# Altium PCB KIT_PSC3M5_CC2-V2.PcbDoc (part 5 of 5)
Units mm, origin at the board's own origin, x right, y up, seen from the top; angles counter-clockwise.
Board outline 131.5 x 87 mm, 6 copper layers (Top Layer, Int1 (GND), Int2 (Sign), Int3 (Sign), Int4 (PWR), Bottom Layer), stack 1.551 mm thick; 371 components, 253 nets, 1359 pads, 837 vias.
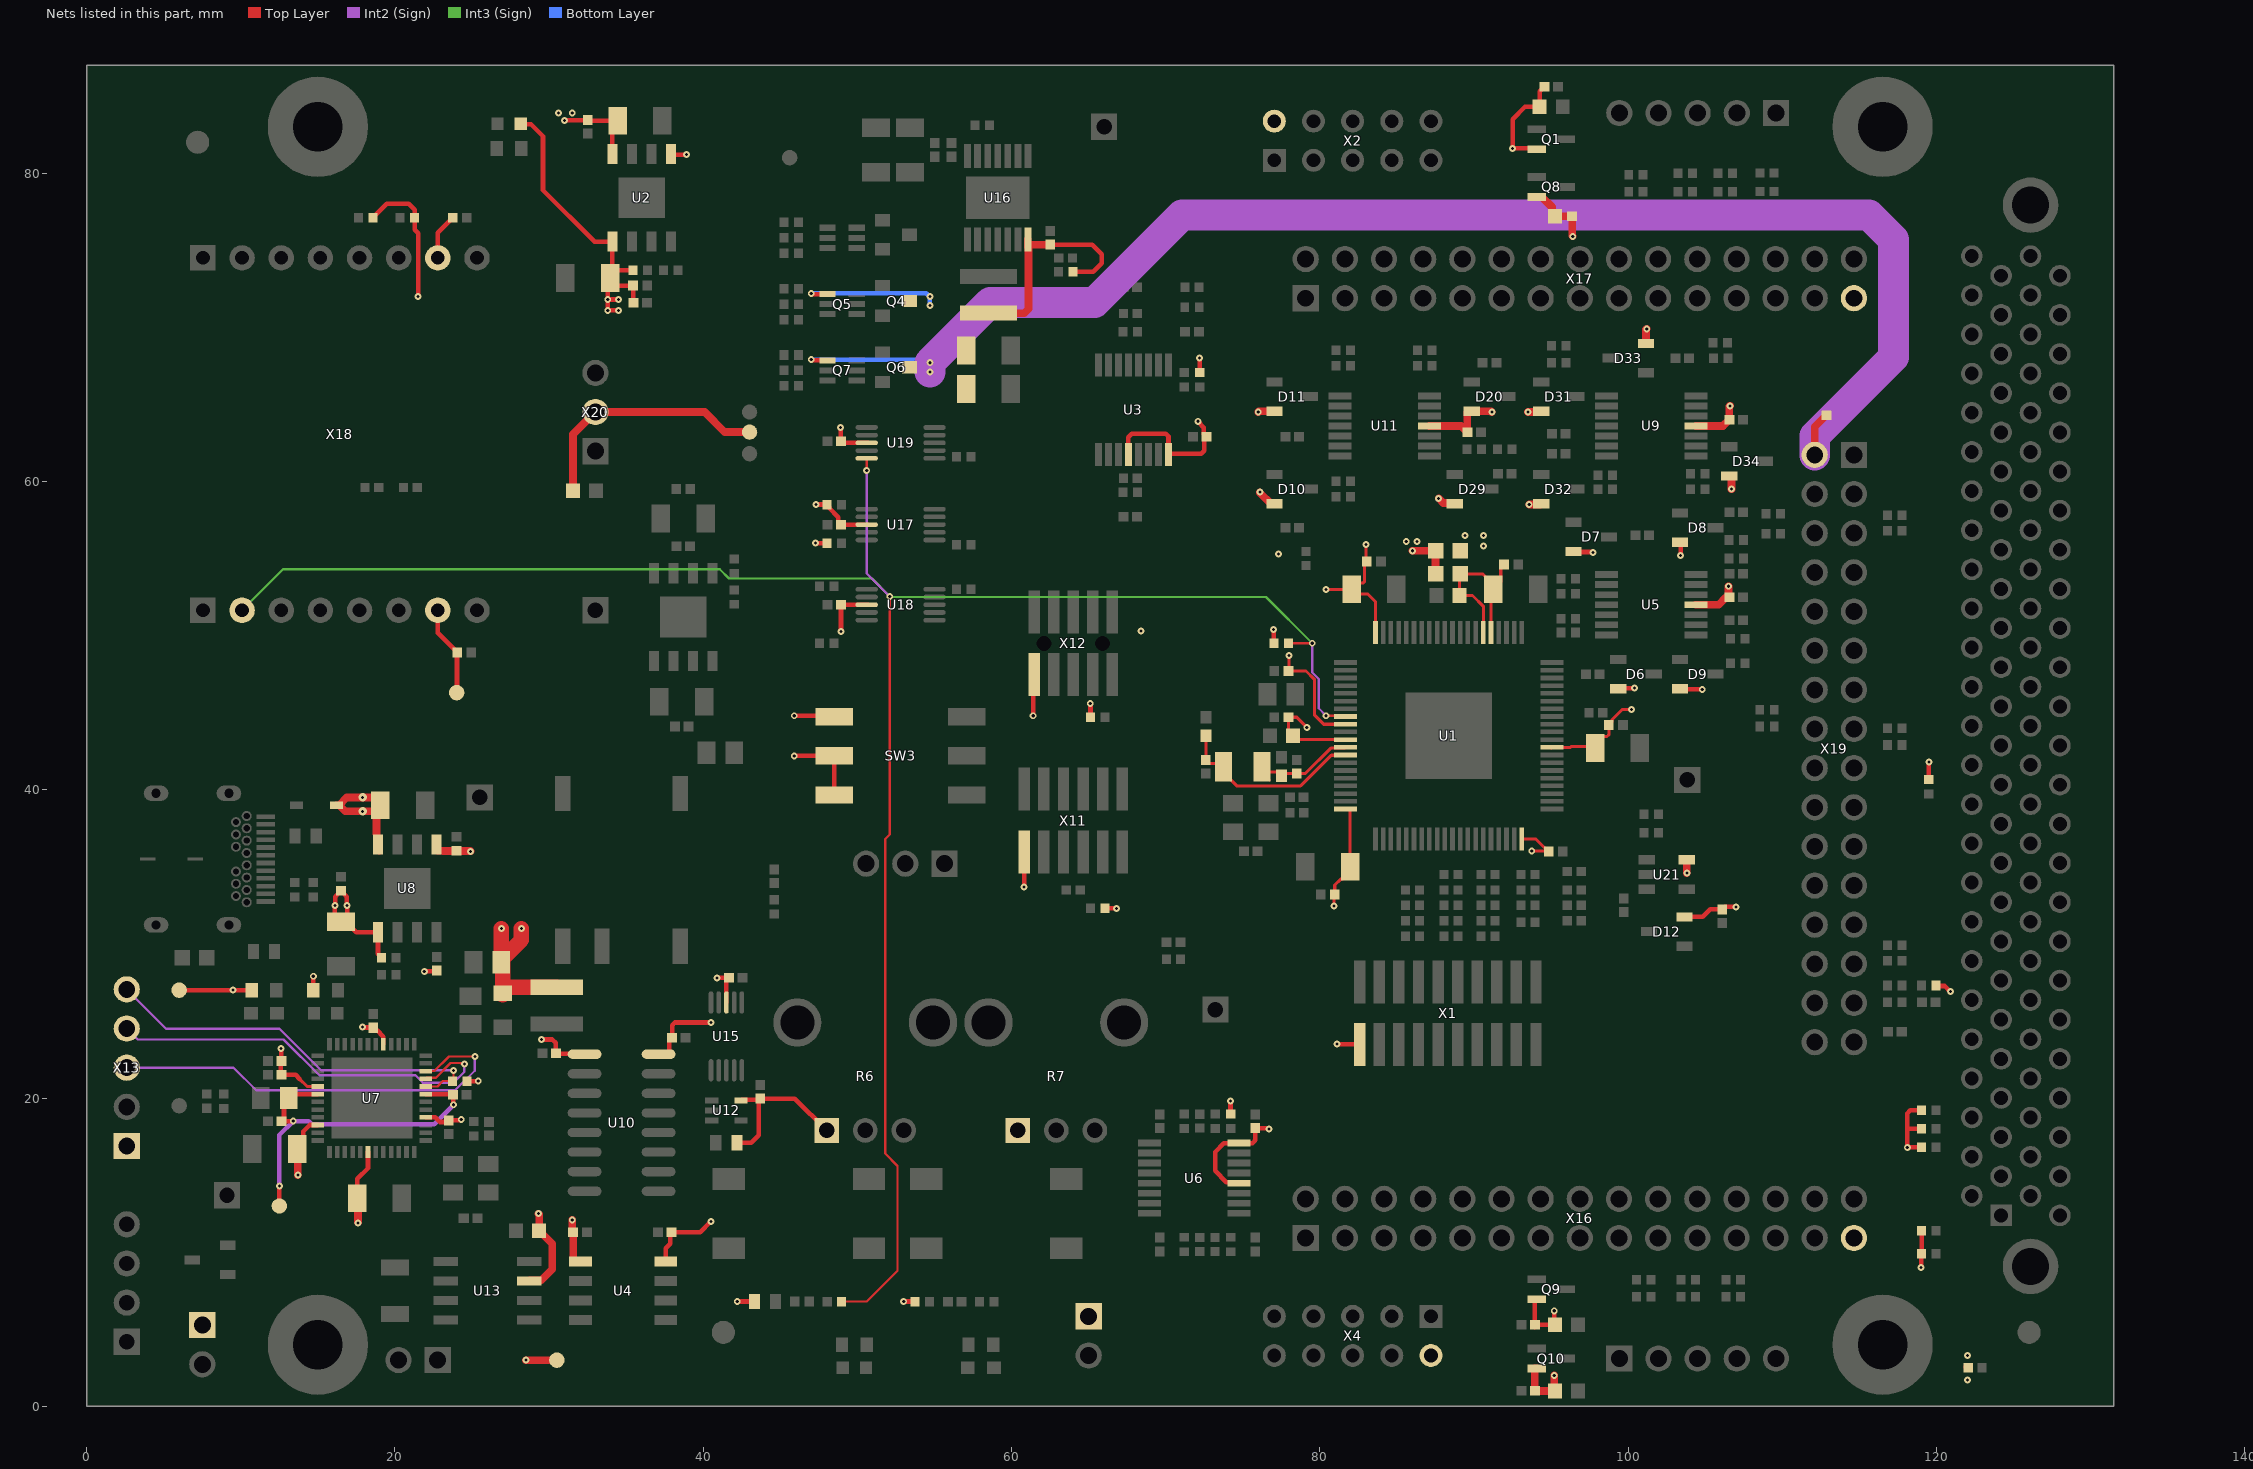
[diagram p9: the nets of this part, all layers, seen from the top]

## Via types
v1: diameter 0.45, hole 0.2, Top Layer to Bottom Layer, tented both sides, 833 vias
v2: diameter 0.55, hole 0.2, Top Layer to Bottom Layer, tented both sides, 4 vias

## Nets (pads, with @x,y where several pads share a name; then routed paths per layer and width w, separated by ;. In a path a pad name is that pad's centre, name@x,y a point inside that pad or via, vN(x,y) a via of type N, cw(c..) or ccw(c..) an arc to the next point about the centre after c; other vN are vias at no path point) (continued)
VDD3.3: C12.2 C14.2 C15.2 C20.1 C29.1 C32.1 C33.2 C34.2 C35.2 C36.2 C65.2 C75.2 C77.2 C81.2 C82.2 C124.2 C125.2 D3.2 JP1.1 L2.1 Q1.2 Q9.2 R5.2 R6.1 R7.1 R14.2 R47.2 R48.2 R49.2 R50.1 R53.2 R70.2 R75.2 R91.2 R99.2 R127.2 R133.2 R140.2 R141.2 R142.2 R143.2 R144.2 R145.2 R162.2 R163.2 SW3.4 SW3.5 SW3.6 TP7.1 U2.1 U3.12 U3.16 U4.8 U6.12 U6.16 U10.16 U12.5 U15.8 U17.8 U18.8 U19.8 X1.1 X11.1 X12.1 X16.29 X17.29 X18.7 | length 129.5
  Top Layer w0.3: R48.2@18.585,77.115 R48.2@18.57,77.1 18.57,77.12 18.71,77.26 18.73,77.26 19.47,78 20.9,78 21.27,77.63 R49.2@21.27,77.1 21.27,76.33 21.5,76.1 v1(21.5,72) ; X18.7@22.78,51.64 22.78,50.17 24.04,48.91 C75.2@24.04,48.9 24.02,48.88 24.02,46.32 TP7.1@24,46.3 ; D3.2@28.15,83.2 28.174,83.176 28.824,83.176 29.6,82.4 29.6,78.9 32.945,75.555 U2.1@34.095,75.555 C15.2@34.095,73.395 ; v1(34.5,71.1) v1(33.8,71.1) v1(33.8,71.8) ; v1(34.5,71.8) v1(33.8,71.8) ; R133.2@35.43,73.7 34.4,73.7 C15.2@34.095,73.395 ; C12.2@35.46,71.6 35.45,71.61 35.45,72.69 C14.2@35.44,72.7 34.4,72.7 33.95,73.15 C15.2@33.95,73.2 ; U10.16@37.1,22.845 37.661,22.845 37.8,22.984 37.8,23.74 C65.2@37.96,23.9 ; U4.8@37.57,9.405 37.57,10.263 37.848,10.54 37.848,11.208 C20.1@37.94,11.3 39.8,11.3 v1(40.5,12) ; C65.2@37.98,23.88 37.98,24.724 38.156,24.9 v1(40.5,24.9) ; v1(40.9,27.8) 40.908,27.808 41.652,27.808 C81.2@41.66,27.8 ; U15.8@41.5,26.2 41.5,27.7 C81.2@41.641,27.841 ; R53.2@42.19,17.1 43.1,17.1 43.6,17.6 43.6,19.86 C77.2@43.7,19.96 ; v1(42.2,6.8) R5.2@43.31,6.8 R5.2@43.305,6.795 ; U12.5@42.45,19.85 42.5,19.9 43.6,19.9 43.68,19.98 C77.2@43.7,19.96 ; C77.2@43.8,19.86 C77.2@43.7,19.96 ; v1(45.9,42.2) SW3.5@48.5,42.2 SW3.6@48.5,39.66 SW3.6@48.44,39.6 ; v1(45.9,44.8) SW3.4@48.54,44.8 ; v1(47.275,56) R70.2@47.96,56 ; v1(47.3,58.5) R127.2@47.886,58.5 ; R6.1@48,17.9 45.94,19.96 C77.2@43.7,19.96 ; R127.2@48.03,58.5 48.03,58.48 48.17,58.34 48.17,58.276 48.765,57.681 48.765,57.36 48.925,57.2 C124.2@48.94,57.2 ; v1(48.9,63.5) 48.92,63.48 48.92,62.62 C82.2@48.94,62.6 49.03,62.51 50.694,62.51 U19.8@50.705,62.5 ; v1(48.919,50.275) 48.929,50.286 48.929,51.989 C125.2@48.94,52 U18.8@50.6,52 U18.8@50.705,52 ; C124.2@49.081,57.2 U17.8@50.6,57.2 U17.8@50.705,57.2 ; v1(53,6.8) R50.1@53.73,6.8 ; v1(60.8,33.7) 60.812,33.713 60.812,35.953 X11.1@60.825,35.965 ; v1(61.4,44.8) 61.4,47.405 X12.1@61.46,47.465 ; v1(65.1,45.6) 65.115,45.585 65.115,44.715 R14.2@65.13,44.7 ; R145.2@66.07,32.3 v1(66.8,32.3) ; U3.12@67.575,61.75 67.575,62.875 67.8,63.1 69.999,63.1 70.175,62.924 U3.16@70.175,61.75 70.2,61.75 70.25,61.8 72.3,61.8 72.5,62 72.5,62.76 C29.1@72.64,62.9 72.625,62.9 72.465,63.06 72.465,63.494 72.1,63.859 v1(72.1,63.9) ; v1(72.2,68) R75.2@72.2,67.07 R75.2@72.34,66.93 ; R91.2@74.2,18.97 v1(74.2,19.8) ; U6.12@74.75,14.475 74.675,14.55 73.926,14.55 73.2,15.276 73.2,16.5 73.757,17.057 74.732,17.057 U6.16@74.75,17.075 75.624,17.075 75.8,17.251 C32.1@75.8,18.06 75.831,18.029 76.671,18.029 v1(76.7,18) ; v1(77,50.4) 77.015,50.385 77.015,49.515 R99.2@77.03,49.5 ; v1(81.1,23.5) 82.55,23.5 X1.1@82.585,23.465 ; C36.2@93.94,5.15 Q9.2@93.94,6.95 ; C36.2@93.94,5.3 C35.2@95.25,5.3 ; Q1.2@94,81.55 93.95,81.6 v1(92.5,81.6) 92.5,83.5 93.3,84.3 C33.2@94.25,84.3 94.25,85.305 94.545,85.6 C34.2@94.56,85.6 ; C35.2@95.2,5.3 v1(95.2,6.2) ; v1(119,9) 119.015,9.015 119.015,9.885 R141.2@119.03,9.9 R142.2@119.03,11.4 R142.2@119.015,11.415 ; R140.2@119.03,16.8 v1(118.1,16.8) 118.1,18 ; R144.2@119.03,18 118.1,18 ; R143.2@119.03,19.2 118.3,19.2 118.1,19 118.1,18 ; R162.2@119.5,40.67 v1(119.5,41.8) ; R163.2@119.97,27.3 120.004,27.266 120.534,27.266 v1(120.9,26.9) ; v1(33.8,71.8) 33.8,73.05 C15.2@33.95,73.2 ; C15.2@33.95,73.2 33.95,73.25 C15.2@34.095,73.395 ; C15.2@33.95,73.2 34.095,73.345 C15.2@34.095,73.395
  Top Layer w0.5: R47.2@122,2.55 R47.2@122.05,2.5
  Int2 (Sign) w0.3: v1(77,50.4) v1@77,50.454
  Int3 (Sign) w0.3: v1@76.946,50.4 v1(77,50.4)
  other v1: 122,1.7 122,3.3 68.4,50.3 77.3,55.3 90.6,55.8 89.4,56.5 90.6,56.5
VDD5: C13.2 C22.2 C23.2 C24.2 C25.2 C37.2 C38.2 C39.2 C40.2 C76.2 C107.2 C131.2 D6.2 D7.2 D8.2 D9.2 D10.2 D11.2 D12.2 D20.2 D29.2 D31.2 D32.2 D33.2 D34.2 Q8.2 Q10.2 TP8.1 U2.5 U2.8 U5.4 U9.4 U11.4 U21.5 X2.2 X4.2 X18.10 X20.2 | length 62.9
  Top Layer w0.3: X18.10@22.78,74.5 22.78,76.13 23.74,77.09 C76.2@23.74,77.1 ; v1(31,83.4) 31.02,83.42 32.48,83.42 C131.2@32.5,83.44 ; C131.2@32.5,83.4 C13.2@34.45,83.4 34.095,83.045 U2.8@34.095,81.245 ; U2.5@37.905,80.915 U2.5@37.905,81.2 ; v1(38.9,81.2) U2.5@37.95,81.2 ; D7.2@96.467,55.449 96.492,55.425 97.675,55.425 v1(97.7,55.4) ; D6.2@99.35,46.55 99.375,46.575 100.375,46.575 v1(100.4,46.6) ; D9.2@103.35,46.55 103.375,46.525 104.775,46.525 v1(104.8,46.5) ; D8.2@103.35,56.05 103.4,56 v1(103.4,55.2) ; D12.2@103.675,31.725 D12.2@103.65,31.75 104.825,31.75 105.315,32.24 C25.2@106.1,32.24 106.26,32.4 v1(107,32.4) ; U2.5@37.905,81.2 U2.5@37.95,81.2 ; U2.5@37.905,81.2 U2.5@37.905,81.245 U2.5@37.95,81.2
  Top Layer w0.5: C107.2@31.55,59.4 31.55,63.05 X20.2@33,64.5 40.1,64.5 41.4,63.2 TP8.1@43,63.2 ; v1(76,64.5) 76.05,64.55 D11.2@77.05,64.55 ; v1(76.1,59.3) 76.1,59.275 76.825,58.55 D10.2@77.05,58.55 ; U11.4@87.1,63.6 89.145,63.6 89.545,63.2 C24.2@89.56,63.2 89.56,64.485 89.625,64.55 D20.2@89.85,64.55 91.1,64.55 v1(91.15,64.5) ; v1(87.7,58.9) 88,58.6 88.7,58.6 D29.2@88.75,58.55 ; v1(93.5,64.5) 94.3,64.5 D31.2@94.35,64.55 ; v1(93.575,58.5) 94.3,58.5 D32.2@94.35,58.55 ; Q10.2@94.05,2.45 93.94,2.45 C40.2@93.94,1 C39.2@95.25,1 95.2,1.05 v1(95.2,2) ; Q8.2@94.05,78.45 94.4,78.45 95.05,77.8 95.05,77.4 C37.2@95.25,77.2 C38.2@96.36,77.2 96.36,75.94 v1(96.4,75.9) ; D33.2@101.15,68.95 101.15,69.85 v1(101.2,69.9) ; v1(103.8,34.6) U21.5@103.8,35.45 ; U5.4@104.4,52 105.859,52 106.299,52.44 106.5,52.44 C22.2@106.56,52.5 106.5,52.56 v1(106.5,53.2) ; U9.4@104.4,63.6 106.145,63.6 106.545,64 C23.2@106.56,64 106.56,64.86 v1(106.6,64.9) ; D34.2@106.55,60.35 106.65,60.35 106.7,60.3 v1(106.7,59.5)
  other v1: 30.6,83.9 31.5,83.9
VDDA: C11.2 C16.2 C17.2 L4.2 U1.65 U1.66 | length 12.9
  Top Layer w0.2: C17.2@89.333,52.717 C17.2@89.05,53 ; U1.66@90.6,50.2 90.6,51.9 89.9,52.6 C17.2@89.05,52.6 C17.2@89.05,53 ; C11.2@90.95,53 91.1,52.85 U1.65@91.1,50.2 ; C16.2@91.94,54.61 C16.2@91.94,54.6 91.73,54.39 91.73,53.48 C11.2@91.25,53 91.25,53.3 90.55,54 L4.2@89.1,54 89.05,53.95 C17.2@89.05,53
VDDC: C51.2 C52.2 C53.2 TP4.1 U7.6 U7.31 | length 23.8
  Top Layer w0.3: TP4.1@12.5,13 v1(12.5,14.3) ; v1(13.4,18.502) C52.2@12.64,18.502 12.801,18.662 12.801,19.703 13.348,20.25 U7.6@15,20.25 ; U7.31@22,20.25 23.71,20.25 C53.2@23.76,20.2 23.78,20.18 23.78,19.585 v1(23.8,19.565)
  Int2 (Sign) w0.3: v1(12.5,14.3) 12.5,17.602 v1(13.4,18.502) 14.4,18.502 14.6,18.302 22.537,18.302 v1(23.8,19.565)
VDDIO: C1.2 C2.2 C3.2 C4.2 C5.2 C6.2 C7.2 C8.2 C9.2 C10.2 L2.2 L4.1 U1.9 U1.11 U1.20 U1.40 U1.49 U1.80 | length 43
  Top Layer w0.15: U1.49@94.975,42.725 U1.49@95,42.7
  Top Layer w0.2: v1(78,48.7) 78,47.74 C8.2@77.96,47.7 79.1,47.7 79.636,47.164 79.636,44.857 80.243,44.25 U1.9@81.65,44.25 ; v1(79.146,44.046) 79.146,44.054 78.5,44.7 C1.2@77.96,44.7 77.96,43.79 C2.2@78.25,43.5 78.5,43.25 U1.11@81.65,43.25 ; v1(80.4,53) C5.2@82.05,53 ; v1(80.9,32.45) 80.9,33.14 C10.2@80.96,33.2 80.96,33.82 81.34,34.2 81.45,34.2 81.95,34.7 C3.2@81.95,35 81.95,38.7 81.9,38.75 U1.20@81.65,38.75 ; v1(83,55.9) 83,54.84 C6.2@83.04,54.8 82.9,54.66 82.9,53.517 82.783,53.4 82.45,53.4 C5.2@82.05,53 ; U1.80@83.6,50.2 83.6,52.2 83.1,52.7 82.35,52.7 C5.2@82.05,53 ; U1.40@93.1,36.8 94,36.8 94.58,36.22 94.63,36.22 94.857,35.993 C7.2@94.857,35.943 ; v1(93.739,36.025) 94.815,36.025 C7.2@94.84,36 ; U1.49@95.05,42.75 96.243,42.75 96.293,42.8 97.75,42.8 C4.2@97.85,42.7 97.85,42.952 98.35,43.452 98.623,43.452 98.74,43.569 C9.2@98.74,44.2 98.95,44.41 98.95,44.55 99.6,45.2 v1(100.2,45.2)
  Top Layer w0.5: v1(86,55.5) L2.2@87.5,55.5 L4.1@87.5,54
  other v1: 85.6,56.1 86.3,56.1
VISO3V3: C41.2 C43.2 C44.2 C45.2 C46.2 C47.2 C48.2 C49.2 C50.2 C63.2 R27.2 R112.1 R113.2 R135.2 TP2.1 U7.5 U7.10 U7.18 U7.28 U7.41 U8.1 U10.1 X13.1 | length 38.2
  Top Layer w0.2: 13.827,21.227 14.304,20.75 U7.5@15,20.75
  Top Layer w0.3: TP2.1@6,27 v1(9.5,27) R112.1@10.7,27 ; v1(12.6,23.202) 12.62,23.182 12.62,22.482 12.67,22.432 12.6,22.362 12.6,21.5 13.554,21.5 13.827,21.227 ; C47.2@13.674,16.502 14.058,16.886 14.058,17.83 14.478,18.25 U7.10@15,18.25 ; R113.2@14.7,27 v1(14.7,27.9) ; C43.2@16.44,33.38 C43.2@16.5,33.44 ; C44.2@16.5,31.45 C44.2@16.525,31.475 ; C45.2@17.55,13.5 17.55,14.752 18.25,15.452 U7.18@18.25,16.5 ; v1(17.9,24.6) 17.92,24.58 18.58,24.58 C49.2@18.6,24.56 18.6,24.545 18.76,24.385 18.839,24.385 19.25,23.974 U7.41@19.25,23.5 ; U8.1@18.828,30.688 U8.1@18.895,30.755 ; R135.2@19.13,29.1 19.13,29.12 18.895,29.355 U8.1@18.895,30.755 ; v1(21.9,28.2) 21.929,28.229 22.669,28.229 C41.2@22.7,28.26 C41.2@22.632,28.328 ; U7.28@22,18.75 22.25,18.75 22.262,18.762 22.599,18.762 22.916,18.445 23.405,18.445 C48.2@23.5,18.54 23.53,18.57 24.27,18.57 v1(24.3,18.6) ; R27.2@24.67,21.1 24.671,21.101 25.399,21.101 v1(25.4,21.102) ; v1(29.5,23.8) 30.2,23.8 30.42,23.58 30.42,22.92 30.468,22.872 32.272,22.872 U10.1@32.3,22.845 ; C43.2@16.5,33.44 16.51,33.44 16.67,33.28 16.67,33.27 16.871,33.069 16.871,32.529 v1(16.9,32.5) 16.9,31.85 C44.2@16.525,31.475 ; C43.2@16.5,33.44 16.49,33.44 16.33,33.28 16.33,33.27 16.129,33.069 16.129,32.529 v1(16.1,32.5) 16.1,31.9 C44.2@16.525,31.475 ; C44.2@16.525,31.475 16.775,31.475 17.495,30.755 U8.1@18.895,30.755
  Top Layer w0.5: C47.2@13.65,16.702 13.7,16.652 v1(13.7,15.002) ; v1@17.6,11.95 C45.2@17.6,13.4
  other v1: 17.6,11.902
VISO5: C19.1 C21.2 C42.2 C64.2 C132.2 D21.1 L5.1 L6.1 TP1.1 U4.1 U8.5 U8.8 U13.3 X30.1 | length 33.2
  Top Layer w0.5: D21.1@16.2,39 D21.1@16.375,39 ; U8.8@18.97,36.04 18.97,36.37 18.82,36.52 18.82,37.123 18.8,37.143 C42.2@18.8,38.7 ; U8.5@22.705,36.442 22.78,36.06 22.835,36.06 23.139,36.024 ccw(c23.199,36.52) 23.197,36.02 24.88,36.02 v1(24.9,36) ; v1(28.5,3) TP1.1@30.5,3 ; U13.3@28.7,8.135 28.75,8.185 29.485,8.185 30.2,8.9 30.2,10.55 29.575,11.175 29.55,11.175 29.35,11.375 C21.2@29.35,11.4 29.35,12.45 v1(29.3,12.5) ; v1(31.5,12.1) 31.5,11.36 C19.1@31.56,11.3 31.56,9.48 31.635,9.405 U4.1@32.03,9.405 ; D21.1@16.375,39 16.775,38.6 v2(17.9,38.6) 18.7,38.6 C42.2@18.8,38.7 ; D21.1@16.375,39 16.875,39.5 v2(17.9,39.5) 18.7,39.5 19.1,39.1 C42.2@19.1,39.05 ; C42.2@18.8,38.7 18.8,38.75 C42.2@19.05,39 C42.2@19.1,39.05 ; C42.2@18.8,38.7 19.1,39 C42.2@19.1,39.05
  Top Layer w1: C64.2@26.9,28.8 26.9,28.95 C64.2@26.95,29 ; v1(26.9,31) 26.9,29.05 C64.2@26.95,29 ; L5.1@27,26.7 27,28.95 C64.2@26.95,29 ; L5.1@27.435,27.185 L6.1@30.5,27.185 ; v1(28.2,31) 28.2,30.25 C64.2@26.95,29
VPWR5V: C78.1 Q6.3 Q7.1 X19.2 | length 95.6
  Top Layer w0.3: v1(47,67.9) 47.05,67.85 Q7.1@48.05,67.85
  Top Layer w0.5: X19.2@112.096,61.722 112.096,63.551 112.845,64.3 C78.1@112.86,64.3
  Int2 (Sign) w2: v1(54.7,67.1) v1(54.7,67.7) 58.61,71.61 65.39,71.61 71.054,77.275 115.625,77.275 117.2,75.7 117.2,68.055 112.096,62.951 X19.2@112.096,61.722
  Bottom Layer w0.3: v1(47,67.9) 54.459,67.9 54.659,67.7 v1(54.7,67.7)
VSW5V: C104.2 C105.2 C106.2 L3.2 Q4.3 Q5.1 R106.2 U16.14 | length 24.4
  Top Layer w0.3: v1(47,72.2) 47.05,72.15 Q5.1@48.05,72.15 ; C104.2@62.5,75.36 65.218,75.36 65.85,74.728 65.85,74.15 65.3,73.6 R106.2@63.97,73.6
  Top Layer w0.5: L3.2@58.5,70.915 60.807,70.915 61.1,71.208 61.1,75.15 61.05,75.2 U16.14@61.05,75.7 ; U16.14@61.1,75.36 C104.2@62.5,75.36
  Bottom Layer w0.3: v1(47,72.2) 54.459,72.2 54.659,72 v1(54.7,72) v1(54.7,71.4)
WCO_IN: C73.2 R2.1 U1.13 Y3.2 | length 12.4
  Top Layer w0.2: R2.1@72.6,43.5 C73.2@72.6,41.94 72.6,41.925 72.81,41.715 73.535,41.715 Y3.2@73.75,41.5 73.75,41.1 74.6,40.25 78.75,40.25 80.738,42.238 81.638,42.238 U1.13@81.65,42.25
WCO_OUT: C70.2 R1.2 U1.12 Y3.1 | length 7.1
  Top Layer w0.15: Y3.1@76.25,41.1 Y3.1@76.725,40.625
  Top Layer w0.2: Y3.1@76.25,41.5 76.6,41.15 77.25,41.15 R1.2@77.5,40.9 77.66,41.06 79.065,41.06 80.705,42.7 81.6,42.7 U1.12@81.65,42.75
XMC42_RST#: R27.1 U7.32 X13.5 | length 26
  Top Layer w0.15: U7.32@22,20.75 22.75,20.75 23.1,21.1 R27.1@23.73,21.1 23.8,21.17 v1(23.8,21.8)
  Int2 (Sign) w0.15: X13.5@2.6,27.05 5.15,24.5 12.5,24.5 15.2,21.8 v1(23.8,21.8)
XMC42_TCK: U7.34 X13.3 | length 28.2
  Top Layer w0.15: U7.34@22,21.75 22.55,21.75 23.5,22.7 v1(25.2,22.7)
  Int2 (Sign) w0.15: X13.3@2.6,21.97 9.53,21.97 11,20.5 23.9,20.5 25.174,21.774 25.174,22.674 v1(25.2,22.7)
XMC42_TMS: U7.33 X13.4 | length 27.1
  Top Layer w0.15: U7.33@22,21.25 22.059,21.309 22.637,21.309 23.603,22.275 24.237,22.275 24.245,22.267 24.433,22.267 v1(24.5,22.2)
  Int2 (Sign) w0.15: X13.4@2.6,24.51 3.31,23.8 12.776,23.8 15.101,21.475 21.325,21.475 21.8,21 23.8,21 24.5,21.7 v1(24.5,22.2)
XRES_L: R99.1 R126.2 U1.8 U19.10 X18.2 | length 138.7
  Top Layer w0.15: R126.2@48.96,6.8 50.6,6.8 52.6,8.8 52.6,15.6 51.8,16.4 51.8,36.8 52.093,37.093 v1(52.093,52.541) ; v1(50.6,60.7) U19.10@50.6,61.5 ; R99.1@77.97,49.5 v1(79.5,49.5) ; v1(80.4,44.8) U1.8@81.7,44.8
  Int2 (Sign) w0.15: v1(50.6,60.7) 50.6,54.034 v1(52.093,52.541) ; v1(79.5,49.5) 79.5,47.6 79.921,47.179 79.921,45.279 v1(80.4,44.8)
  Int3 (Sign) w0.15: X18.2@10.08,51.64 12.74,54.3 41.072,54.3 41.672,53.7 50.934,53.7 v1(52.093,52.541) 52.134,52.5 76.5,52.5 v1(79.5,49.5)
pads on no net: ADJ_1.ADJ ADJ_2.ADJ ADJ_3.ADJ R6.MH1 R6.MH2 R7.MH1 R7.MH2 U2.3 U2.7 U3.13 U3.14 U3.15 U6.13 U6.14 U6.15 U7.2 U7.8 U7.9 U7.19 U7.21 U7.24 U7.25 U7.26 U7.38 U7.42 U7.43 U7.44 U8.3 U8.7 U13.5 U14.3 U14.7 U15.7 U15.9 U16.1 U16.3 U19.4 U19.6 U19.7 U20.8 X1.7 X1.11 X1.13 X2.1 X2.4 X4.1 X4.4 X10.A2 X10.A3 X10.A8 X10.A10 X10.A11 X10.B2 X10.B3 X10.B8 X10.B10 X10.B11 X12. X12.7 X15.A26 X15.A27 X15.A32 X15.A37 X15.A38 X15.A39 X15.A40 X15.A44 X15.A48 X15.B26 X15.B27 X15.B32 X15.B37 X15.B38 X15.B39 X15.B40 X15.B42 X15.B43 X15.B47

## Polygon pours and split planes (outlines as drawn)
VDDIO on Top Layer "VDDIO_L01_P051" (solid, remove dead copper, pour order 51): 85.2,56.5 85.2,55.3 87,53.5 88.1,53.5 88.1,56.5
NetL3_1 on Top Layer "NETL3_1_L01_P065" (solid, remove dead copper, pour order 65): 58.2,76.5 59.3,76.5 59.3,74.2 59.7,73.8 60.4,73.8 60.4,72.7 56.6,72.7 56.6,73.8 57.8,73.8 58.2,74.2
VDCDC5 on Top Layer "VDCDC5_L01_P066" (solid, remove dead copper, pour order 66): 38.7,62.4 38.7,55 39.5,55 40.1,54.4 40.1,53.3 41.4,53.3 41.4,54.5 42.4,54.5 42.4,57.3 40,59.7 40,62.4
VSW5V on Top Layer "VSW5V_L01_P068" (solid, remove dead copper, pour order 68): 52.9,72.3 52.9,71.1 56,68 56,65 58,65 58,70.4 60.4,70.4 60.4,71.4 55.9,71.4 55,72.3
VDD5 on Top Layer "VDD5_L01_P069" (solid, remove dead copper, pour order 69): 30.3,84.3 34.7,84.3 34.7,80.5 33,80.5 33,83 30.3,83
VDD3.3 on Top Layer "VDD3.3_L01_P070" (solid, remove dead copper, pour order 70): 33.3,76.2 33.3,70.8 35.8,70.8 35.8,74.5 34.7,74.5 34.7,76.2
VISO5 on Top Layer "VISO5_L01_P071" (solid, remove dead copper, pour order 71): 19.5,40 19.5,35.8 18,35.8 18,38.2 15.7,38.2 15.7,40
VISO3V3 on Top Layer "VISO3V3_L01_P072" (solid, remove dead copper, pour order 72): 15.6,33.7 15.6,30 19.4,30 19.4,31.5 17.2,33.7
VDDA on Top Layer "VDDA_L01_P054" (solid, remove dead copper, pour order 54): 88.5,54.6 88.5,51.9 90.1,51.9 90.4,51.6 90.4,49.3 91.3,49.3 91.3,51.3 92.3,52.3 92.3,55 91.5,55 91.1,54.6
VDD3.3 on Top Layer "VDD3.3_L01_P064" (solid, remove dead copper, pour order 64): 88.5,57 88.5,54.8 91,54.8 91,57
VDCDC7 on Top Layer "VDCDC7_L01_P067" (solid, remove dead copper, pour order 67): 38,38.5 38,47.3 39.5,47.3 39.5,49 41,49 41,38.5
GNDISO on Top Layer "GNDISO_L01_P080" (solid, remove dead copper, pour order 80): 0.5,40.5 24.7,40.5 31.9,33.3 31.9,5.4 27,0.5 0.5,0.5
GND on Top Layer "GND_L01_P079" (solid, remove dead copper, pour order 79): 0.5,86.5 0.5,51 6.3,45.2 35.1,45.2 38,42.3 38,28.6 38,15.3 37.6,14.9 37.6,0.5 131,0.5 131,86.5
GNDISO on Bottom Layer "GNDISO_L06_P078" (solid, remove dead copper, pour order 78): 0.5,40.5 24.7,40.5 31.9,33.3 31.9,5.4 27,0.5 0.5,0.5
GND on Bottom Layer "GND_L06_P077" (solid, remove dead copper, pour order 77): 0.5,86.5 0.5,51 6.3,45.2 35.1,45.2 38,42.3 38,28.6 38,15.3 37.6,14.9 37.6,0.5 131,0.5 131,86.5
GNDISO on Int2 (Sign) "GNDISO_L03_P074" (solid, remove dead copper, pour order 74): 0.5,40.5 24.7,40.5 31.9,33.3 31.9,5.4 27,0.5 0.5,0.5
GND on Int2 (Sign) "GND_L03_P073" (solid, remove dead copper, pour order 73): 0.5,86.5 0.5,51 6.3,45.2 35.1,45.2 38,42.3 38,28.6 38,15.3 37.6,14.9 37.6,0.5 131,0.5 131,86.5
GNDISO on Int3 (Sign) "GNDISO_L04_P076" (solid, remove dead copper, pour order 76): 0.5,40.5 24.7,40.5 31.9,33.3 31.9,5.4 27,0.5 0.5,0.5
GND on Int3 (Sign) "GND_L04_P075" (solid, remove dead copper, pour order 75): 0.5,86.5 0.5,51 6.3,45.2 35.1,45.2 38,42.3 38,28.6 38,15.3 37.6,14.9 37.6,0.5 131,0.5 131,86.5
VDD5 on Int4 (PWR) (split plane): 53.898,75 53.906,74.961 53.928,74.928 53.961,74.906 54,74.898 56,74.898 56.039,74.906 56.072,74.928 56.094,74.961 56.102,75 56.102,84.398 89.898,84.398 89.898,77 89.906,76.961 89.928,76.928 89.961,76.906 90,76.898 107.898,76.898 107.898,31.102 101.902,31.102 101.902,35.6 101.902,44.4 101.894,44.439 101.872,44.472 91.102,55.242 91.102,56.8 91.094,56.839 91.072,56.872 89.472,58.472 89.439,58.494 89.4,58.502 74.602,58.502 74.602,73 74.594,73.039 74.572,73.072 74.539,73.094 74.5,73.102 32.5,73.102 32.461,73.094 32.428,73.072 32.406,73.039 32.398,73 32.398,70.5 32.406,70.461 32.428,70.428 34.398,68.458 34.398,63.302 30.602,63.302 30.602,73 30.594,73.039 30.572,73.072 30.539,73.094 30.5,73.102 2,73.102 1.961,73.094 1.928,73.072 1.906,73.039 1.898,73 1.898,52.5 1.906,52.461 1.928,52.428 4.928,49.428 4.961,49.406 5,49.398 37.858,49.398 39.898,47.358 39.898,4.5 39.906,4.461 39.928,4.428 39.961,4.406 40,4.398 96.398,4.398 96.398,0.51 38,0.51 38,42.3 35.1,45.2 6.3,45.2 0.51,50.99 0.51,86.49 53.898,86.49
VISO3V3 on Int4 (PWR) (split plane): 16.898,37.5 16.906,37.461 16.928,37.428 16.961,37.406 17,37.398 21.958,37.398 25.898,33.458 25.898,30 25.906,29.961 25.928,29.928 25.961,29.906 26,29.898 29.898,29.898 29.898,14.042 26.458,10.602 9.542,10.602 6.572,13.572 6.539,13.594 6.5,13.602 0.51,13.602 0.51,40.5 16.898,40.5
VISO5 on Int4 (PWR) (split plane): 31.9,35.1 31.9,5.4 27.01,0.51 0.51,0.51 0.51,13.398 6.458,13.398 9.428,10.428 9.461,10.406 9.5,10.398 26.5,10.398 26.539,10.406 26.572,10.428 30.072,13.928 30.094,13.961 30.102,14 30.102,30 30.094,30.039 30.072,30.072 30.039,30.094 30,30.102 26.102,30.102 26.102,33.5 26.094,33.539 26.072,33.572 22.072,37.572 22.039,37.594 22,37.602 17.102,37.602 17.102,40.5 26.5,40.5
VDD3.3 on Int4 (PWR) (split plane): 113.298,73.16 113.306,73.121 113.328,73.088 113.361,73.066 113.4,73.058 128.398,73.058 128.398,25.102 125,25.102 124.961,25.094 124.928,25.072 124.906,25.039 124.898,25 124.898,18.952 120.848,14.902 113.4,14.902 113.361,14.894 113.328,14.872 113.306,14.839 113.298,14.8 113.298,12.2 113.306,12.161 113.328,12.128 113.361,12.106 113.4,12.098 130.99,12.098 130.99,0.51 96.602,0.51 96.602,4.5 96.594,4.539 96.572,4.572 96.539,4.594 96.5,4.602 40.102,4.602 40.102,47.4 40.094,47.439 40.072,47.472 37.972,49.572 37.939,49.594 37.9,49.602 5.042,49.602 2.102,52.542 2.102,72.898 30.398,72.898 30.398,63.2 30.406,63.161 30.428,63.128 30.461,63.106 30.5,63.098 34.5,63.098 34.539,63.106 34.572,63.128 34.594,63.161 34.602,63.2 34.602,68.5 34.594,68.539 34.572,68.572 32.602,70.542 32.602,72.898 74.398,72.898 74.398,58.4 74.406,58.361 74.428,58.328 74.461,58.306 74.5,58.298 89.358,58.298 90.898,56.758 90.898,55.302 87.202,55.302 87.202,56.5 87.194,56.539 87.172,56.572 87.139,56.594 87.1,56.602 79.7,56.602 79.661,56.594 79.628,56.572 79.606,56.539 79.598,56.5 79.598,52.142 77.028,49.572 77.006,49.539 76.998,49.5 76.998,34.2 76.998,31.2 77.006,31.161 77.028,31.128 77.828,30.328 77.861,30.306 77.9,30.298 82.2,30.298 82.239,30.306 82.272,30.328 87.442,35.498 101.698,35.498 101.698,31 101.706,30.961 101.728,30.928 101.761,30.906 101.8,30.898 108,30.898 108.039,30.906 108.072,30.928 108.094,30.961 108.102,31 108.102,77 108.094,77.039 108.072,77.072 108.039,77.094 108,77.102 90.102,77.102 90.102,84.398 113.298,84.398
VDDIO on Int4 (PWR) (split plane): 86.998,55.2 87.006,55.161 87.028,55.128 87.061,55.106 87.1,55.098 90.958,55.098 101.698,44.358 101.698,35.702 87.4,35.702 87.361,35.694 87.328,35.672 82.158,30.502 77.942,30.502 77.202,31.242 77.202,34.2 77.202,49.458 79.772,52.028 79.794,52.061 79.802,52.1 79.802,56.398 86.998,56.398
PWR_IN_5V on Int4 (PWR) (split plane): 130.99,12.302 113.502,12.302 113.502,14.698 120.89,14.698 120.929,14.706 120.962,14.728 125.072,18.838 125.094,18.871 125.102,18.91 125.102,24.898 128.5,24.898 128.539,24.906 128.572,24.928 128.594,24.961 128.602,25 128.602,73.16 128.594,73.199 128.572,73.232 128.539,73.254 128.5,73.262 113.502,73.262 113.502,84.5 113.494,84.539 113.472,84.572 113.439,84.594 113.4,84.602 56,84.602 55.961,84.594 55.928,84.572 55.906,84.539 55.898,84.5 55.898,75.102 54.102,75.102 54.102,86.49 130.99,86.49
GNDISO on Int1 (GND) (split plane): 26.5,40.5 31.9,35.1 31.9,5.4 27.01,0.51 0.51,0.51 0.51,40.5
GND on Int1 (GND) (split plane): 130.99,0.51 38,0.51 38,42.3 35.1,45.2 6.3,45.2 0.51,50.99 0.51,86.49 130.99,86.49
AGND on Int1 (GND) (split plane): 129.198,71.358 129.198,68.142 127.158,66.102 125.742,66.102 125.172,66.672 125.139,66.694 125.1,66.702 123.5,66.702 123.461,66.694 123.428,66.672 123.028,66.272 123.006,66.239 122.998,66.2 122.998,60.6 122.998,55.7 123.006,55.661 123.028,55.628 126.798,51.858 126.798,24.142 125.128,22.472 125.106,22.439 125.098,22.4 125.098,19.242 124.758,18.902 124.1,18.902 124.061,18.894 124.028,18.872 122.558,17.402 120.742,17.402 120.502,17.642 120.502,21.958 121.042,22.498 123.1,22.498 123.139,22.506 123.172,22.528 124.672,24.028 124.694,24.061 124.702,24.1 124.702,25.6 124.694,25.639 124.672,25.672 122.572,27.772 122.539,27.794 122.5,27.802 119.4,27.802 119.361,27.794 119.328,27.772 118.128,26.572 118.106,26.539 118.098,26.502 116.242,26.502 114.872,27.872 114.839,27.894 114.8,27.902 99.342,27.902 98.102,29.142 98.102,36.758 99.422,38.078 101.042,39.698 104.6,39.698 104.639,39.706 104.672,39.728 104.694,39.761 104.702,39.8 104.702,42.9 104.694,42.939 104.672,42.972 101.672,45.972 101.639,45.994 101.6,46.002 97.342,46.002 96.102,47.242 96.102,55.8 96.094,55.839 96.072,55.872 92.372,59.572 92.339,59.594 92.3,59.602 85,59.602 84.961,59.594 84.928,59.572 80.058,54.702 74.142,54.702 73.602,55.242 73.602,68.958 74.942,70.298 110.398,70.298 110.398,58.7 110.406,58.661 110.428,58.628 111.328,57.728 111.361,57.706 111.4,57.698 115.7,57.698 115.739,57.706 115.772,57.728 119.572,61.528 119.594,61.561 119.602,61.6 119.602,67.958 124.242,72.598 127.958,72.598

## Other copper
Top Layer:
  rectangle net VBUS_C: 12.5,38.7 14.2,40.2
  rectangle net VDD3.3: 121.7,1.4 122.4,3.6
  rectangle net VPWR5V: 52.9,66.8 55,68
  rectangle net PWR_IN_5V: 52.9,75.4 55,76.6
  rectangle net V5V: 49.4,65.3 52.1,66.8
  rectangle net V5V: 49.4,69.6 52.1,71.1
  rectangle net V5V: 49.4,73.9 52.1,75.4
  rectangle net PWR_IN_24V: 48.2,79.1 49.9,81.5
  rectangle net PWR_IN_24V: 55.8,80 58,81.4
  rectangle net PWR_IN_24V: 56.7,80.3 58,82.3
  rectangle net GND: 48.5,81.9 54.3,83.9
  rectangle net PWR_IN_24V: 50.2,79.3 56.5,81.4
Int3 (Sign):
  rectangle net PWR_IN_24V: 48.5,79.181 49.746,81.3
Bottom Layer:
  text "KIT_PSC3M5_CC2-V2 / www.hitex.com" at 4.2,86.5 h1.27 r90
Int1 (GND) (plane layer: these items are gaps in the copper):
  pour cut-out: 0.033,51.467 6.3,45.2 35.1,45.2 38,42.3 38,0.51 27.01,0.51 31.9,5.4 31.9,35.1 26.5,40.5 0.043,40.5
  lines w0.2: 123.1,60.4 123.1,66.2 123.5,66.6 125.1,66.6 125.7,66 127.2,66 129.3,68.1 129.3,71.4 128,72.7 124.2,72.7 119.5,68 119.5,61.6 115.7,57.8 111.4,57.8 110.5,58.7 110.5,70.4 74.9,70.4 73.5,69 73.5,55.2 74.1,54.6 80.1,54.6 85,59.5 92.3,59.5 96,55.8 96,47.2 97.3,45.9 101.6,45.9 104.6,42.9 104.6,39.8 101,39.8 99.35,38.15 98,36.8 98,29.1 99.3,27.8 114.8,27.8 116.2,26.4 118.2,26.4 118.2,26.5 119.4,27.7 122.5,27.7 124.6,25.6 124.6,24.1 123.1,22.6 121,22.6 120.4,22 120.4,17.6 120.7,17.3 122.6,17.3 124.1,18.8 124.8,18.8 125.2,19.2 125.2,22.4 126.9,24.1 126.9,51.9 123.1,55.7 123.1,60.6
Int4 (PWR) (plane layer: these items are gaps in the copper):
  pour cut-out: -0.067,51.567 6.3,45.2 26.7,45.2 35.1,45.2 38,42.3 38,0 26.5,0 31.9,5.4 31.9,35.1 26.5,40.5 -0.057,40.5
  lines w0.2: 0,13.5 6.5,13.5 9.5,10.5 26.5,10.5 30,14 30,30 26,30 26,33.5 22,37.5 17,37.5 17,42.7 ; 54,87 54,75 56,75 56,84.5 78,84.5 113.4,84.5 113.4,73.16 128.5,73.16 128.5,25 125,25 125,18.91 120.89,14.8 113.4,14.8 113.4,12.2 131.5,12.2 ; 90,84.5 90,77 108,77 108,31 101.8,31 101.8,35.6 ; 96.5,0 96.5,4.5 40,4.5 40,47.4 37.9,49.5 5,49.5 2,52.5 2,73 30.5,73 30.5,63.2 34.5,63.2 34.5,68.5 32.5,70.5 32.5,73 74.5,73 74.5,58.4 89.4,58.4 91,56.8 91,55.2 ; 131.5,66 131.5,71.7 ; 87.4,35.6 87.4,35.6 ; 87.4,35.6 82.2,30.4 77.9,30.4 77.1,31.2 77.1,34.2 77.1,49.5 79.7,52.1 79.7,56.5 87.1,56.5 87.1,55.2 91,55.2 ; 87.4,35.6 101.8,35.6 ; 91,55.2 101.8,44.4 101.8,35.6 ; 118.5,87.1 118.5,87.1

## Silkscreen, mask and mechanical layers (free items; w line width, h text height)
Top Overlay:
  drawing of 2705 lines, arcs and shapes, not listed
  text "VDD3.3" at 23.401,84.517 h1.52
  text "GND" at 64.6,80.317 h1.52
  text "Encoder 1" at 65.5,78.015 h1.52
  text "HALL 1" at 109.2,76.8 h1.52
  text "5V / selection" at 35.5,68.2 h1.52
  text "V5V" at 35.7,66.5 h1.52
  text "VDD5" at 35.701,64.417 h1.52
  text "5V USB" at 35.7,62.417 h1.52
  text "DAP/" at 64.2,55.217 h1.52
  text "JTAG" at 64.097,54.017 h1.52
  text "GND" at 31.5,48.917 h1.52
  text "TB" at 49.4,47.3 h1.52
  text "DAP" at 53.7,47.3 h1.52
  text "Trace_Box" at 62.8,42.7 h1.52
  text "GND" at 105.42,40.557 h1.52
  text "GNDISO" at 26.883,32.7 h1.52 r90
  text "TB_UART" at 48.629,31.6 h1.52 r90
  text "TX" at 52.4,31.6 h1.52 r45
  text "RX" at 54.7,31.6 h1.52 r45
  text "GND" at 49.488,30.912 h1.52 r45
  text "AUX" at 4.599,25.117 h1.52
  text "DEBUG" at 9.7,23.817 h1.52
  text "GND" at 71.62,23.157 h1.52
  text "ETM Header" at 80.185,21.8 h1.52 r90
  text "OBD" at 5.183,21.6 h1.52 r90
  text "KIT_PSC3M5_CC2" at 90.3,16.9 h2.54
  text "POT1" at 50.8,15.917 h1.52
  text "POT2" at 66.683,13.4 h1.52 r90
  text "GNDISO" at 6.8,11.217 h1.52
  text "RESET" at 47.2,7.917 h1.52
  text "USER" at 59.4,7.917 h1.52
  text "HALL 2" at 111.5,7.8 h1.52
  text "CAN" at 5.283,7.3 h1.52 r90
  text "LED1" at 48.2,0.7 h1.52
  text "LED2" at 56.3,0.7 h1.52
  text "Encoder 2" at 65.5,0.515 h1.52
  text "CAN-TERM" at 18.9,0.217 h1.52
Bottom Overlay:
  drawing of 45 lines, arcs and shapes, not listed
  text "AN_A0" at 97.329,80.001 h1.52 r90
  text "AN_A1" at 99.829,80.001 h1.52 r90
  text "AN_A2" at 102.429,80.001 h1.52 r90
  text "AN_B0" at 104.929,80.001 h1.52 r90
  text "AN_B1" at 107.529,80.001 h1.52 r90
  text "AN_B2" at 110.029,80.001 h1.52 r90
  text "PWR_ / IN_5V" at 116.2,79.3 h1.52 r90
  text "P7.1" at 79.5,79 h1.52 r90
  text "P7.2" at 82.1,79 h1.52 r90
  text "P7.3" at 84.8,79 h1.52 r90
  text "P9.3" at 87.083,79 h1.52 r90
  text "P9.0" at 89.583,79 h1.52 r90
  text "P9.1" at 92.183,79 h1.52 r90
  text "P9.2" at 94.683,79 h1.52 r90
  text "GND" at 112.483,79 h1.52 r90
  text "P7.0" at 109.883,70.6 h1.52 r90
  text "P5.1" at 79.313,70.5 h1.52 r90
  text "P5.0" at 81.908,70.5 h1.52 r90
  text "P5.2" at 84.883,70.5 h1.52 r90
  text "P5.3" at 87.083,70.5 h1.52 r90
  text "AN_B5" at 89.629,70.501 h1.52 r90
  text "AN_B4" at 92.129,70.501 h1.52 r90
  text "AN_A3" at 94.629,70.501 h1.52 r90
  text "AN_B3" at 97.229,70.501 h1.52 r90
  text "P2.1" at 99.8,70.5 h1.52 r90
  text "P2.3" at 102.283,70.5 h1.52 r90
  text "P6.2" at 104.783,70.5 h1.52 r90
  text "P6.3" at 107.283,70.5 h1.52 r90
  text "GND" at 112.483,70.5 h1.52 r90
  text "VDD3.3" at 114.983,70.499 h1.52 r90
  text "PWR_ / IN_5V" at 116.3,18.5 h1.52 r90
  text "P0.1" at 79.483,18.1 h1.52 r90
  text "P7.4" at 82.1,18.1 h1.52 r90
  text "P7.5" at 84.8,18.1 h1.52 r90
  text "P7.6" at 87.183,18.1 h1.52 r90
  text "P7.7" at 89.7,18.1 h1.52 r90
  text "P8.0" at 92.183,18.1 h1.52 r90
  text "P8.1" at 94.783,18.1 h1.52 r90
  text "P8.2" at 97.383,18.1 h1.52 r90
  text "P8.3" at 99.883,18.1 h1.52 r90
  text "P8.4" at 102.483,18.1 h1.52 r90
  text "P8.5" at 104.983,18.1 h1.52 r90
  text "P6.0" at 107.383,18.1 h1.52 r90
  text "P6.1" at 109.983,18.1 h1.52 r90
  text "GND" at 112.483,18.1 h1.52 r90
  text "VDD / 3.3" at 115.6,9.8 h1.52 r90
  text "P0.0" at 79.483,9.5 h1.52 r90
  text "P3.0" at 82.083,9.5 h1.52 r90
  text "P3.1" at 84.783,9.5 h1.52 r90
  text "P5.2" at 87.183,9.5 h1.52 r90
  text "P3.3" at 89.683,9.5 h1.52 r90
  text "P4.0" at 92.183,9.5 h1.52 r90
  text "P4.1" at 94.8,9.5 h1.52 r90
  text "P4.2" at 97.3,9.5 h1.52 r90
  text "P4.3" at 99.883,9.5 h1.52 r90
  text "P4.4" at 102.5,9.5 h1.52 r90
  text "P4.5" at 104.983,9.5 h1.52 r90
  text "P4.6" at 107.583,9.5 h1.52 r90
  text "P4.7" at 110.1,9.5 h1.52 r90
  text "GND" at 112.583,9.5 h1.52 r90
Top Frame:
  drawing of 72 lines, arcs and shapes, not listed
  text "1" at -53.783,191.391 h1.78
  text "2" at -4.744,191.391 h1.78
  text "3" at 44.515,191.391 h1.78
  text "4" at 93.808,191.391 h1.78
  text "5" at 143.084,191.391 h1.78
  text "6" at 192.106,191.391 h1.78
  text "7" at 241.636,191.391 h1.78
  text "8" at 290.658,191.391 h1.78
  text "A" at -75.915,157.406 h1.78
  text "A" at 312.705,157.406 h1.78
  text "B" at -75.915,86.794 h1.78
  text "B" at 312.705,86.794 h1.78
  text "C" at -75.915,16.182 h1.78
  text "C" at 312.705,16.182 h1.78
  text "D" at -75.915,-53.922 h1.78
  text "D" at 312.705,-53.922 h1.78
  text "ENGINEER:" at 197.77,-54.1 h1.14
  text "TITLE:" at 235.87,-54.1 h1.14
  text "NAME" at 199.04,-57.148 h1.78
  text ".myPCBName" at 237.14,-57.148 h1.78
  text "PCB DESIGNER:" at 197.77,-61.593 h1.14
  text "NAME" at 199.04,-64.641 h1.78
  text "DATE:" at 197.77,-69.34 h1.14
  text "PART NO.:" at 235.87,-69.34 h1.14
  text "REV:" at 289.21,-69.34 h1.14
  text "Hitex GmbH" at 155.75,-70.68 h1.78
  text ".PRINT_DATE" at 199.04,-72.388 h1.78
  text "-A1" at 290.48,-72.388 h1.78
  text "Greschbachstr. 12" at 155.75,-73.22 h1.78
  text "76229 Karlsruhe, Germany" at 155.75,-75.76 h1.78
  text "FILE NAME:" at 197.77,-76.96 h1.14
  text "DWG NO:" at 235.87,-76.96 h1.14
  text "SCALE:" at 289.21,-76.96 h1.14
  text "www.hitex.com" at 155.75,-78.3 h1.78
  text ".PCB_FILE_NAME_NO_PATH" at 199.04,-80.008 h1.78
  text ".Print_Scale" at 290.48,-80.008 h1.78
  text "1" at -53.783,-85.469 h1.78
  text "2" at -4.744,-85.469 h1.78
  text "3" at 44.515,-85.469 h1.78
  text "4" at 93.808,-85.469 h1.78
  text "5" at 143.084,-85.469 h1.78
  text "6" at 192.106,-85.469 h1.78
  text "7" at 241.636,-85.469 h1.78
  text "8" at 290.658,-85.469 h1.78
Bottom Frame:
  drawing of 72 lines, arcs and shapes, not listed
  text "8" at -52.598,191.391 h1.78
  text "7" at -3.576,191.391 h1.78
  text "6" at 45.954,191.391 h1.78
  text "5" at 94.976,191.391 h1.78
  text "4" at 144.252,191.391 h1.78
  text "3" at 193.545,191.391 h1.78
  text "2" at 242.804,191.391 h1.78
  text "1" at 291.843,191.391 h1.78
  text "A" at -74.645,157.406 h1.78
  text "A" at 313.975,157.406 h1.78
  text "B" at -74.645,86.794 h1.78
  text "B" at 313.975,86.794 h1.78
  text "C" at -74.645,16.182 h1.78
  text "C" at 313.975,16.182 h1.78
  text "D" at -74.645,-53.922 h1.78
  text "D" at 313.975,-53.922 h1.78
  text "TITLE:" at 2.19,-54.1 h1.14
  text "ENGINEER:" at 40.29,-54.1 h1.14
  text ".myPCBName" at 0.92,-57.148 h1.78
  text "NAME" at 39.02,-57.148 h1.78
  text "PCB DESIGNER:" at 40.29,-61.593 h1.14
  text "NAME" at 39.02,-64.641 h1.78
  text "REV:" at -51.15,-69.34 h1.14
  text "PART NO.:" at 2.19,-69.34 h1.14
  text "DATE:" at 40.29,-69.34 h1.14
  text "Hitex GmbH" at 82.31,-70.68 h1.78
  text "-A1" at -52.42,-72.388 h1.78
  text ".PRINT_DATE" at 39.02,-72.388 h1.78
  text "Greschbachstr. 12" at 82.31,-73.22 h1.78
  text "76229 Karlsruhe, Germany" at 82.31,-75.76 h1.78
  text "SCALE:" at -51.15,-76.96 h1.14
  text "DWG NO:" at 2.19,-76.96 h1.14
  text "FILE NAME:" at 40.29,-76.96 h1.14
  text "www.hitex.com" at 82.31,-78.3 h1.78
  text ".Print_Scale" at -52.42,-80.008 h1.78
  text ".PCB_FILE_NAME_NO_PATH" at 39.02,-80.008 h1.78
  text "8" at -52.598,-85.469 h1.78
  text "7" at -3.576,-85.469 h1.78
  text "6" at 45.954,-85.469 h1.78
  text "5" at 94.976,-85.469 h1.78
  text "4" at 144.252,-85.469 h1.78
  text "3" at 193.545,-85.469 h1.78
  text "2" at 242.804,-85.469 h1.78
  text "1" at 291.843,-85.469 h1.78
3. Outline:
  lines w0.1: 4,41.6 cw(c4,42.6) 4,43.6 31,43.6 cw(c31,42.6) 31,41.6 4,41.6 ; 33.7,11.2 ccw(c34.7,11.2) 35.7,11.2 35.7,23.1 ccw(c34.7,23.1) 33.7,23.1 33.7,11.2 ; 34.9,26.5 ccw(c35.9,26.5) 36.9,26.5 36.9,39.9 ccw(c35.9,39.9) 34.9,39.9 34.9,26.5
  lines w0.2: 0,0 131.5,0 131.5,87 0,87 0,0
4. Dimensions:
  circle w0.2: c116.5,4 r1.6
  circle w0.2: c126.095,9.075 r1.2
  circle w0.2: c126.095,77.925 r1.2
  circle w0.2: c116.5,83 r1.6
  circle w0.2: c15,83 r1.6
  circle w0.2: c15,4 r1.6
  text "2x" at 113.4,69.6 h1.52
  text "4x" at 21.1,3.1 h1.52
  text "Mechanikplan / Mechanical drawing" at 237.14,-60.196 h1.78
  text ".myPCBNumber" at 237.14,-72.388 h1.78
  text "MPL" at 237.14,-80.008 h1.78
Mechanical 5:
  lines w4: 5,42.6 33.2,42.6 36,39.8 36,25.5 34.7,24.2 34.7,10.2
Panel:
  circle w0.2: c5,179 r0.75
  circle w0.2: c5,179 r1.5
  circle w0.2: c116.5,170 r1.6
  circle w0.2: c126.095,164.925 r1.2
  circle w0.2: c126.5,179 r1.5
  circle w0.2: c126.5,179 r0.75
  circle w0.2: c126.5,-5 r0.75
  circle w0.2: c126.5,-5 r1.5
  circle w0.2: c5,-5 r1.5
  circle w0.2: c5,-5 r0.75
  circle w0.2: c126.095,96.075 r1.2
  circle w0.2: c116.5,91 r1.6
  circle w0.2: c15,170 r1.6
  circle w0.2: c15,91 r1.6
  lines w0.2: 0,0 131.5,0 ; 0,0 0,-10 131.5,-10 131.5,0 ; 0,0 0,87 ; 0,87 0,174 ; 0,87 131.5,87 ; 0,174 0,184 131.5,184 131.5,174 ; 0,174 131.5,174 ; 131.5,0 131.5,87 ; 131.5,87 131.5,174
  text "Panel Array 2x1" at 68.5,126.9 h5.08
  text "Fiducial (3x)" at 6.7,-4.1 h1.52
Top Assembly:
  lines w0.15: 86.9,37 87.2,36.7 87.2,34.3 ; 87.7,31.4 87.2,31.9 87.2,34.3 ; 87.7,33.8 87.2,34.3 ; 91.6,31.3 92.7,30.5
  lines w0.305: 19.1,77.2 19.6,77.2 ; 21.7,77.2 22.7,77.2 ; 25.9,77.2 26.9,77.2
  text "Bestueckungsplan Bestueckungsseite" at 237.14,-60.196 h1.78
  text "Assembly Top Layer" at 237.14,-63.244 h1.78
  text ".myBGNumber" at 237.14,-72.388 h1.78
  text "VARIANT NAME:" at 251.834,-76.96 h1.14
  text "BPL" at 237.14,-80.008 h1.78
  text ".VariantName" at 253.104,-80.008 h1.78
Bottom Assembly:
  text "Bestueckungsplan Loetseite" at 0.92,-60.196 h1.78
  text "Assembly Bottom Layer" at 0.92,-63.244 h1.78
  text ".myBGNumber" at 0.92,-72.388 h1.78
  text "VARIANT NAME:" at -13.774,-76.96 h1.14
  text ".VariantName" at -15.044,-80.008 h1.78
  text "BPL" at 0.92,-80.008 h1.78
Drill Drawing:
  text ".Legend" at 172.9,-47.4 h1.52
  text "Bohrplan / Drill drawing" at 237.14,-60.196 h1.78
  text ".myPCBNumber" at 237.14,-72.388 h1.78
  text "DPL" at 237.14,-80.008 h1.78

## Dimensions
33.7,23.1 to 35.7,23.1 on 4. Dimensions
34.9,39.9 to 36.9,39.9 on 4. Dimensions
31,41.6 to 31,43.6 on 4. Dimensions
3,42.6 to 32,42.6 on 4. Dimensions
34.7,24.1 to 34.7,10.2 on 4. Dimensions
35.9,40.9 to 35.9,25.5 on 4. Dimensions
3,42.6 to 0,0 on 4. Dimensions
34.7,10.2 to 0,0 on 4. Dimensions
35.9,25.5 to 0,0 on 4. Dimensions
128.7,182.3 to 134.4,182.3 on Panel
129,-7.3 to 134.7,-7.3 on Panel
132,0 to 137.7,0 on Panel
132.076,173.992 to 137.776,173.992 on Panel
0,-10 to 5,-6.9 on Panel
0,-10 to 6.5,-5 on Panel
0,0 to 0,-10 on Panel
131.5,87 to 137.2,87 on Panel
126.095,77.925 to 121.6,73.9 on 4. Dimensions
15,4 to 18.4,6.7 on 4. Dimensions
0,0 to 126.095,77.925 on 4. Dimensions
0,0 to 126.095,9.075 on 4. Dimensions
0,0 to 126.095,9.075 on 4. Dimensions
0,0 to 15,83 on 4. Dimensions
0,0 to 15,4 on 4. Dimensions
0,0 to 116.5,4 on 4. Dimensions
0,0 to 15,4 on 4. Dimensions
0,87 to 0,0 on 4. Dimensions
0,0 to 131.5,0 on 4. Dimensions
